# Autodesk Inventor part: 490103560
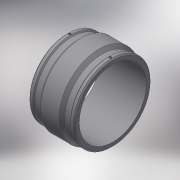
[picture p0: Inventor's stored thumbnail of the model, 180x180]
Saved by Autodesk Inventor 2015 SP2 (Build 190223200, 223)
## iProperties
Created: 2017-06
Part Number: 490103560
Material: Generic
Description: PLASSON COUPLER 560
Document SubType Name: Modeling
Designer: KIM
Mass: 16398.8 g
Surface Area: 10528.4 cm^2
Volume: 16398.8 cm^3
Density: 1 g/cm^3
Appearance: Default
Author: KIM
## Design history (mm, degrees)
derived "490103.ipt"
feature "Solid1::490103.ipt"
tag "TaggingFeature1"
body "Solid1"
other parameters: "d13" = 376, "d15" = 188, "d16" = 188, "d22" = 634, "d23" = 674, "d24" = 614.98, "d25" = 135 deg, "d26" = 150.4, "d27" = 135 deg, "d29" = 317, "d35" = 15, "d39" = 0, "d40" = 4, "d41" = 14, "d42" = 0, "d43" = 135 deg, "d44" = 41.36, "d46" = 6, "d47" = 0, "L_" = 376, "L_1" = 188, "D_" = 674, "A_" = 317, "d_2" = 12
